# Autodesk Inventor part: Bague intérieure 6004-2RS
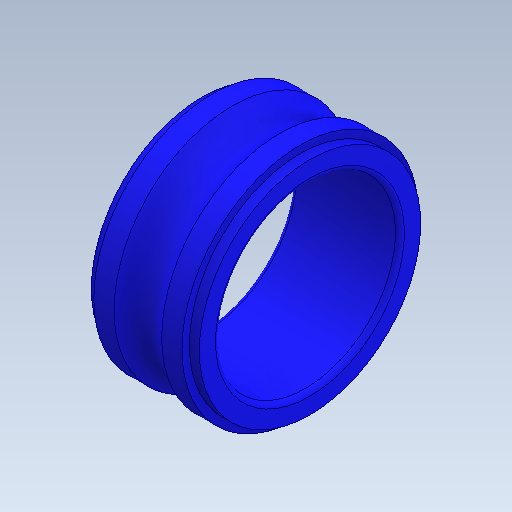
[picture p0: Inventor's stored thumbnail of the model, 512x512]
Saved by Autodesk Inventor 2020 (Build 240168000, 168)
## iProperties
Created: 2003-06
Part Number: Bague intérieure 6004-2RS
Material: Générique
Document SubType Name: Modeling
Designer: Bruno
Density: 1 g/cm^3
Appearance: Par défaut
Author: Bruno
Sending System: SolidWorks 2011
Last Author: frederic
Last Saved: 2012-02-20
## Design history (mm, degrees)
feature "Base-Révolution"
node "Solide1"
